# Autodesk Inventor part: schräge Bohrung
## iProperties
Author: Bernhard Ruf/Armin Keller
Created: 2001-08
Part Number: schräge Bohrung
Material: Standard
Document SubType Name: Modellieren
Designer: Bernhard Ruf
Control State: 0
Master: False
Checked Out: False
PropertySet Name: Design Tracking Control
Shininess: 69.0
PropertySet Name: _Private Model Information
Density: 0.0
Volumn: 0.0
Area: 0.0
PropertySet Name: Model Information
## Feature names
1. Extrusion1
2. Drehung1 [Revolution]
3. Extrusion2
4. Bohrung1 [Hole]
